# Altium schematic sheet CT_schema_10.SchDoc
size 147 x 119 mm
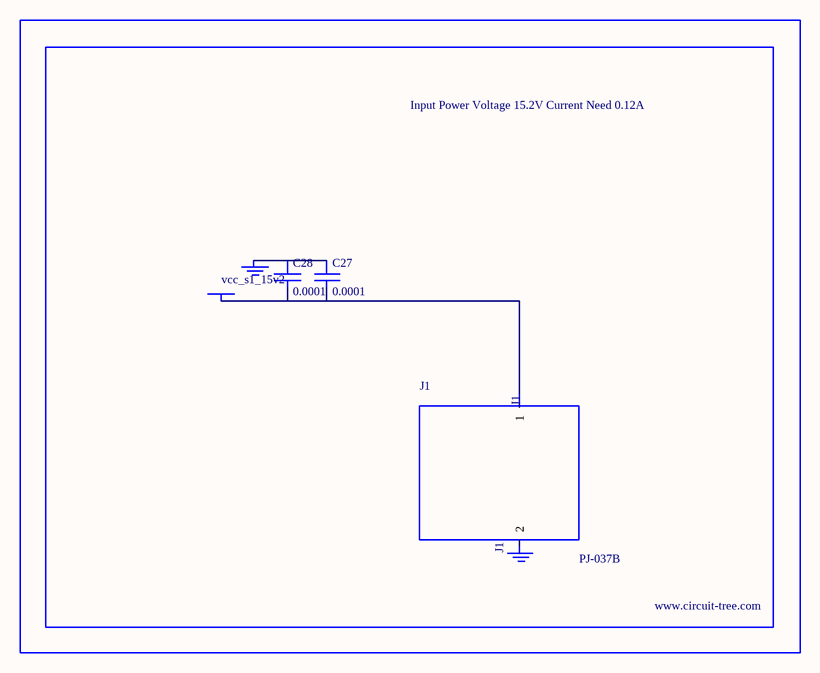
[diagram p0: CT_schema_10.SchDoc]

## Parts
BORDER9  (no value)
C27  0.0001  [EXV-9H]
C28  0.0001  [EXV-9H]
GND_INSTANCE_9_0  (no value)
GND_INSTANCE_9_1  (no value)
J1  PJ-037B  [PJ-037B_PACKAGE]
POWER_INSTANCE_9_0  vcc_s1_15v2

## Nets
NetC27_1: C27.1 C28.1 GND_INSTANCE_9_0.0(GND)
NetC27_2: C27.2 C28.2 J1.1 POWER_INSTANCE_9_0.0(PWR)

Not connected (* = marked no-connect by the designer): GND_INSTANCE_9_1 0(GND); J1 2

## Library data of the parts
BORDER9 = BORDER_PAGE9
C27 C28 = EDK107M035A9HAA
GND_INSTANCE_9_0 GND_INSTANCE_9_1 = GND
POWER_INSTANCE_9_0 = PWR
